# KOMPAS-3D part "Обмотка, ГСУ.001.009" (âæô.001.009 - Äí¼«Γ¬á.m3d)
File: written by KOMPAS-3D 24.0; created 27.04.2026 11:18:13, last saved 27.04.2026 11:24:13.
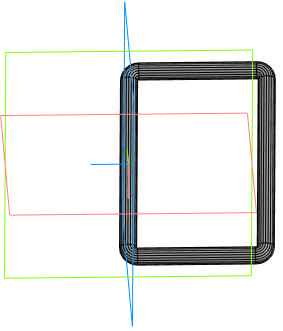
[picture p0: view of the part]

Document properties: Автор: User7; Полное имя файла: C:\Users\User7\Desktop\олимп\ГСУ.001.009 - Обмотка.m3d

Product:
- Part/product: Обмотка  | designation ГСУ.001.009
    Масса: 0.009726

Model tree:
1. Эскиз:1
2. Эскиз:2
3. Элемент по траектории:1
     Длина траектории = 134.366

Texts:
  ГСУ.001.009
  Шаг 1
  Шаг 2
